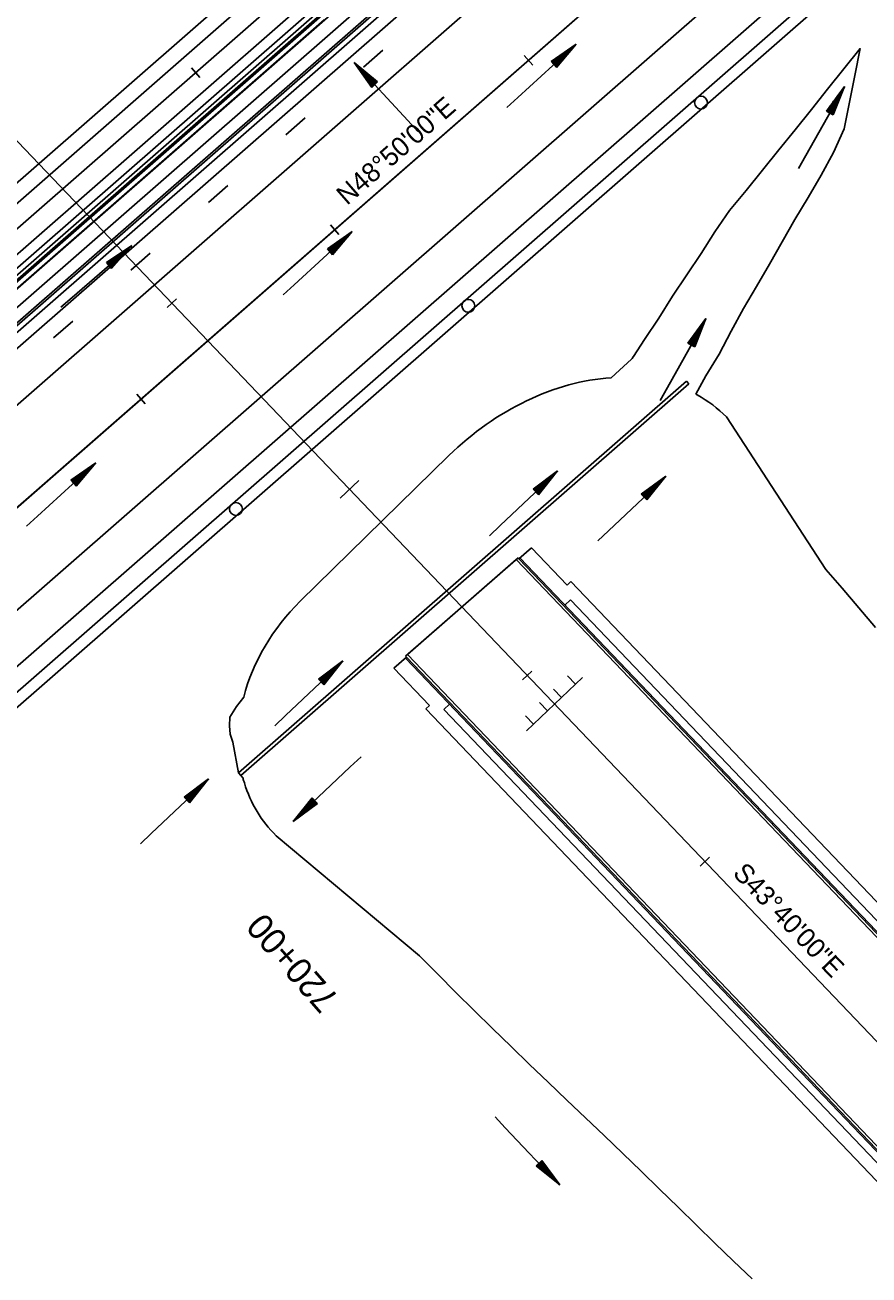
# Model space of a CAD drawing. Extents: x 1300404 to 1323571, y 234004 to 252077.
# Drawn here: x 1310716.2 to 1311044.1, y 240637.1 to 241122.9 of the extents above; entities that cross this region are included whole.
import ezdxf

# ---------------------------------------------------------------- set-up
doc = ezdxf.new("R2010")
doc.units = 0
for name, color, linetype in [('MOT Stage 1', 7, 'Continuous'), ('R_Barrel', 7, 'Continuous'), ('R_Barrier Wall', 7, 'Continuous'), ('R_Bridge', 7, 'Continuous'), ('R_Bridge Wall', 7, 'Continuous'), ('R_Const Limits', 7, 'Continuous'), ('R_Curb', 7, 'Continuous'), ('R_Draft', 7, 'Continuous'), ('R_Flow Arrows', 7, 'Continuous'), ('R_Horz Alg Major Ticks', 7, 'Continuous'), ('R_Horz Alg Minor Ticks', 7, 'Continuous'), ('R_Horz Alg Station Annot', 7, 'Continuous'), ('R_Horz Alg Tangents Text', 7, 'Continuous'), ('R_Lane Edge', 7, 'Continuous'), ('R_Pipe Culvert', 7, 'Continuous'), ('R_Proposed', 7, 'Continuous'), ('R_Shoulder', 7, 'Continuous'), ('R_Sidewalk Edge', 7, 'Continuous'), ('R_Temp Barrier Wall', 7, 'Continuous'), ('R_Temp Travel Stripe', 7, 'Continuous')]:
    doc.layers.add(name, color=color, linetype=linetype)

msp = doc.modelspace()

# ---------------------------------------------------------------- linework, layer by layer
at = {"layer": 'MOT Stage 1'}
for p, q in [((1310921.92, 240858.93), (1310932.77, 240869.29)), ((1310930.05, 240866.7), (1310926.95, 240869.96)), ((1310924.63, 240861.52), (1310921.52, 240864.78)), ((1310911.06, 240848.58), (1310921.92, 240858.93)), ((1310919.2, 240856.34), (1310916.1, 240859.6)), ((1310913.78, 240851.17), (1310910.67, 240854.42))]:
    msp.add_line(p, q, dxfattribs=at)
at = {"layer": 'R_Barrel'}
for centre in [(1310978.82, 241092.72), (1310888.47, 241013.74), (1310798.13, 240934.76)]:
    msp.add_circle(centre, 2.5, dxfattribs=at)
at = {"layer": 'R_Barrier Wall'}
for p, q in [((1309593.62, 240046.84), (1310923.44, 241209.65)), ((1309594.93, 240045.34), (1310924.76, 241208.15))]:
    msp.add_line(p, q, dxfattribs=at)
at = {"layer": 'R_Bridge'}
for p, q in [((1310864.08, 240877.52), (1310907.78, 240915.74)), ((1310907.78, 240915.74), (1310908.12, 240915.39)), ((1310908.12, 240915.39), (1310912.99, 240919.65)), ((1310912.99, 240919.65), (1310926.82, 240905.21)), ((1310926.82, 240905.21), (1310928.27, 240906.59)), ((1310859.51, 240872.89), (1310864.41, 240877.18)), ((1310864.41, 240877.18), (1310864.08, 240877.52)), ((1310873.32, 240858.43), (1310859.51, 240872.89)), ((1310871.88, 240857.04), (1310873.32, 240858.43))]:
    msp.add_line(p, q, dxfattribs=at)
at = {"layer": 'R_Bridge Wall'}
for p, q in [((1310799.12, 240832.17), (1310973.27, 240984.44)), ((1310800, 240831.16), (1310974.14, 240983.43)), ((1310974.14, 240983.43), (1310973.27, 240984.44)), ((1310800, 240831.16), (1310799.12, 240832.17))]:
    msp.add_line(p, q, dxfattribs=at)
at = {"layer": 'R_Const Limits'}
for p, q in [((1310988.78, 240970.54), (1311027.32, 240911.3)), ((1310988.78, 240970.54), (1311027.32, 240911.3)), ((1310823.12, 240898.9), (1310880.92, 240955.54)), ((1310823.12, 240898.9), (1310880.92, 240955.54)), ((1310799.12, 240832.17), (1310800.89, 240830.14)), ((1310799.12, 240832.17), (1310800.89, 240830.14)), ((1310813.77, 240807.78), (1310869.51, 240761.06)), ((1310813.77, 240807.78), (1310869.51, 240761.06))]:
    msp.add_line(p, q, dxfattribs=at)
for points in [[(1310943.96, 240985.79), (1310947.24, 240988.69), (1310951.89, 240992.93), (1310952.15, 240993.31), (1310952.55, 240993.92), (1310952.65, 240994.08), (1310956.95, 241000.61), (1310962.45, 241008.98), (1310967.82, 241017.42), (1310973.35, 241025.76), (1310978.89, 241034.1), (1310984.27, 241042.54), (1310989.93, 241050.81), (1310996.41, 241058.59), (1311002.8, 241066.42), (1311009.11, 241074.29), (1311015.49, 241082.13), (1311021.8, 241090.01), (1311028.05, 241097.93), (1311034.31, 241105.84), (1311040.66, 241113.69), (1311038.66, 241103.24), (1311036.53, 241092.87), (1311034.46, 241082.46), (1311030.27, 241073.32), (1311025.53, 241064.5), (1311020.53, 241055.84), (1311015.36, 241047.28), (1311010.37, 241038.61), (1311005.4, 241029.93), (1311000.43, 241021.25), (1310995.33, 241012.65), (1310990.62, 241003.82), (1310985.89, 240995), (1310980.66, 240986.47), (1310976.81, 240979.35)], [(1310943.96, 240985.79), (1310947.24, 240988.69), (1310951.89, 240992.93), (1310952.15, 240993.31), (1310952.55, 240993.92), (1310952.65, 240994.08), (1310956.95, 241000.61), (1310962.45, 241008.98), (1310967.82, 241017.42), (1310973.35, 241025.76), (1310978.89, 241034.1), (1310984.27, 241042.54), (1310989.93, 241050.81), (1310996.41, 241058.59), (1311002.8, 241066.42), (1311009.11, 241074.29), (1311015.49, 241082.13), (1311021.8, 241090.01), (1311028.05, 241097.93), (1311034.31, 241105.84), (1311040.66, 241113.69), (1311038.66, 241103.24), (1311036.53, 241092.87), (1311034.46, 241082.46), (1311030.27, 241073.32), (1311025.53, 241064.5), (1311020.53, 241055.84), (1311015.36, 241047.28), (1311010.37, 241038.61), (1311005.4, 241029.93), (1311000.43, 241021.25), (1310995.33, 241012.65), (1310990.62, 241003.82), (1310985.89, 240995), (1310980.66, 240986.47), (1310976.81, 240979.35)], [(1311027.33, 240911.29), (1311033.68, 240903.93), (1311040.19, 240896.32), (1311046.68, 240888.7)], [(1311027.33, 240911.29), (1311033.68, 240903.93), (1311040.19, 240896.32), (1311046.68, 240888.7)], [(1310799.12, 240832.17), (1310796.95, 240844.17), (1310795.93, 240847.21), (1310795.63, 240850.43), (1310795.75, 240853.8), (1310798.3, 240857.98), (1310801.17, 240861.66)], [(1310799.12, 240832.17), (1310796.95, 240844.17), (1310795.93, 240847.21), (1310795.63, 240850.43), (1310795.75, 240853.8), (1310798.3, 240857.98), (1310801.17, 240861.66)], [(1310998.7, 240635.54), (1310991.49, 240642.48), (1310984.28, 240649.42), (1310977.09, 240656.38), (1310969.93, 240663.37), (1310962.78, 240670.37), (1310955.65, 240677.39), (1310948.44, 240684.33), (1310941.18, 240691.23), (1310933.93, 240698.14), (1310926.7, 240705.05), (1310919.48, 240711.99), (1310912.27, 240718.93), (1310905.07, 240725.89), (1310897.89, 240732.85), (1310890.72, 240739.83), (1310883.57, 240746.83), (1310876.53, 240753.94), (1310869.51, 240761.06), (1310869.51, 240761.06), (1310869.51, 240761.06), (1310869.51, 240761.06), (1310869.51, 240761.06), (1310869.51, 240761.06), (1310869.51, 240761.06), (1310869.51, 240761.06), (1310869.51, 240761.06)], [(1310998.7, 240635.54), (1310991.49, 240642.48), (1310984.28, 240649.42), (1310977.09, 240656.38), (1310969.93, 240663.37), (1310962.78, 240670.37), (1310955.65, 240677.39), (1310948.44, 240684.33), (1310941.18, 240691.23), (1310933.93, 240698.14), (1310926.7, 240705.05), (1310919.48, 240711.99), (1310912.27, 240718.93), (1310905.07, 240725.89), (1310897.89, 240732.85), (1310890.72, 240739.83), (1310883.57, 240746.83), (1310876.53, 240753.94), (1310869.51, 240761.06), (1310869.51, 240761.06), (1310869.51, 240761.06), (1310869.51, 240761.06), (1310869.51, 240761.06), (1310869.51, 240761.06), (1310869.51, 240761.06), (1310869.51, 240761.06), (1310869.51, 240761.06)]]:
    msp.add_lwpolyline(points, dxfattribs=at)
for centre, major_axis, ratio, start_param, end_param in [((1310926.5, 240908.22), (-62.28, -62.32), 0.745616, 3.84485, 4.698226), ((1310926.5, 240908.22), (-62.28, -62.32), 0.745616, 3.84485, 4.698226), ((1310926.5, 240908.22), (-62.28, -62.32), 0.745616, 3.358393, 3.367118), ((1310926.5, 240908.22), (-62.28, -62.32), 0.745616, 3.358393, 3.367118), ((1310926.5, 240908.22), (-62.28, -62.32), 0.745616, 3.141593, 3.358393), ((1310926.5, 240908.22), (-62.28, -62.32), 0.745616, 3.141593, 3.358393), ((1310862.67, 240857.7), (48.9, 49.92), 0.817242, 1.545592, 2.183789), ((1310862.67, 240857.7), (48.9, 49.92), 0.817242, 1.545592, 2.183789), ((1310862.67, 240857.7), (48.9, 49.92), 0.817242, 2.691395, 2.723332), ((1310862.67, 240857.7), (48.9, 49.92), 0.817242, 2.691395, 2.723332), ((1310862.67, 240857.7), (48.9, 49.92), 0.817242, 2.723644, 3.141593), ((1310862.67, 240857.7), (48.9, 49.92), 0.817242, 2.723644, 3.141593)]:
    msp.add_ellipse(centre, major_axis=major_axis, ratio=ratio, start_param=start_param, end_param=end_param, dxfattribs=at)
at = {"layer": 'R_Curb'}
for p, q in [((1310908.12, 240915.39), (1311065.94, 240750.04)), ((1310908.49, 240915.72), (1311067.92, 240748.69)), ((1310864.04, 240876.85), (1311009.39, 240724.57)), ((1310864.41, 240877.18), (1311008.13, 240726.61)), ((1311008.13, 240726.61), (1311199.03, 240526.61)), ((1311009.39, 240724.57), (1311198.47, 240526.48))]:
    msp.add_line(p, q, dxfattribs=at)
at = {"layer": 'R_Draft'}
for p, q in [((1308396.96, 238971.92), (1312368.36, 242444.53)), ((1308407.83, 238959.5), (1312379.22, 242432.11)), ((1308447.32, 238914.33), (1312418.71, 242386.94)), ((1308458.18, 238901.91), (1312429.57, 242374.52)), ((1309184.47, 239689.08), (1312131.36, 242265.86)), ((1309037.78, 239548.19), (1312137.61, 242258.71)), ((1309193.69, 239678.54), (1312140.58, 242255.32)), ((1309413.86, 239721.62), (1312065.67, 242040.38)), ((1309410.89, 239725), (1311987.97, 241978.41)), ((1309410.89, 239725), (1311987.97, 241978.41))]:
    msp.add_line(p, q, dxfattribs=at)
at = {"layer": 'R_Flow Arrows'}
for p, q in [((1310920.59, 241108.65), (1310930.28, 241115.48)), ((1310922.65, 241106.41), (1310930.28, 241115.48)), ((1310853.18, 241100.72), (1310844.02, 241108.24)), ((1310850.97, 241098.64), (1310844.02, 241108.24)), ((1310920.59, 241108.65), (1310922.65, 241106.41)), ((1310850.97, 241098.64), (1310853.18, 241100.72)), ((1311027.56, 241089.44), (1311034.57, 241098.99)), ((1311030.22, 241087.97), (1311034.57, 241098.99)), ((1311027.56, 241089.44), (1311030.22, 241087.97)), ((1310833.66, 241035.82), (1310843.35, 241042.65)), ((1310835.72, 241033.58), (1310843.35, 241042.65)), ((1310747.81, 241030.54), (1310757.64, 241037.17)), ((1310749.82, 241028.26), (1310757.64, 241037.17)), ((1310833.66, 241035.82), (1310835.72, 241033.58)), ((1310747.81, 241030.54), (1310749.82, 241028.26)), ((1310973.77, 240999.27), (1310980.78, 241008.82)), ((1310976.43, 240997.8), (1310980.78, 241008.82)), ((1310973.77, 240999.27), (1310976.43, 240997.8)), ((1310733.97, 240945.92), (1310743.66, 240952.75)), ((1310736.03, 240943.68), (1310743.66, 240952.75)), ((1310913.58, 240942.49), (1310923.08, 240949.56)), ((1310915.69, 240940.3), (1310923.08, 240949.56)), ((1310733.97, 240945.92), (1310736.03, 240943.68)), ((1310955.66, 240940.48), (1310965.17, 240947.56)), ((1310957.78, 240938.3), (1310965.17, 240947.56)), ((1310913.58, 240942.49), (1310915.69, 240940.3)), ((1310955.66, 240940.48), (1310957.78, 240938.3)), ((1310830.17, 240868.66), (1310839.68, 240875.73)), ((1310832.29, 240866.47), (1310839.68, 240875.73)), ((1310830.17, 240868.66), (1310832.29, 240866.47)), ((1310777.97, 240822.77), (1310787.48, 240829.84)), ((1310780.09, 240820.58), (1310787.48, 240829.84)), ((1310777.97, 240822.77), (1310780.09, 240820.58)), ((1310827.75, 240822.53), (1310820.36, 240813.27)), ((1310829.86, 240820.34), (1310827.75, 240822.53)), ((1310829.86, 240820.34), (1310820.36, 240813.27)), ((1310916.94, 240681.6), (1310914.75, 240679.49)), ((1310914.75, 240679.49), (1310924.01, 240672.1)), ((1310916.94, 240681.6), (1310924.01, 240672.1))]:
    msp.add_line(p, q, dxfattribs=at)
for points in [[(1310903.41, 241090.79), (1310907.64, 241094.7), (1310930.28, 241115.48)], [(1310921.42, 241107.76), (1310926, 241111.96), (1310928.35, 241114.11)], [(1310920.8, 241108.43), (1310922.53, 241110.02)], [(1310921.01, 241108.21), (1310924.47, 241111.38)], [(1310921.21, 241107.98), (1310925.79, 241112.19), (1310926.41, 241112.75)], [(1310921.83, 241107.31), (1310926.41, 241111.51), (1310928.76, 241113.66)], [(1310922.03, 241107.09), (1310926.61, 241111.29), (1310927.23, 241111.85)], [(1310922.24, 241106.86), (1310925.7, 241110.04)], [(1310868.86, 241081.51), (1310864.95, 241085.73), (1310844.13, 241108.34)], [(1310851.85, 241099.47), (1310847.59, 241104), (1310845.42, 241106.32)], [(1310852.3, 241099.89), (1310848.04, 241104.42), (1310845.86, 241106.74)], [(1310851.63, 241099.26), (1310847.37, 241103.79), (1310846.8, 241104.4)], [(1310852.52, 241100.09), (1310848.26, 241104.62), (1310847.69, 241105.23)], [(1310922.44, 241106.64), (1310924.18, 241108.23)], [(1310851.41, 241099.05), (1310848.19, 241102.48)], [(1310852.74, 241100.3), (1310849.52, 241103.73)], [(1310851.19, 241098.84), (1310849.58, 241100.56)], [(1310852.96, 241100.51), (1310851.35, 241102.22)], [(1311016.73, 241067.16), (1311019.56, 241072.18), (1311034.7, 241098.92)], [(1311028.36, 241089), (1311031.36, 241094.45), (1311031.77, 241095.17)], [(1311028.62, 241088.86), (1311031.63, 241094.3), (1311033.18, 241097.08)], [(1311029.16, 241088.56), (1311032.16, 241094), (1311033.71, 241096.78)], [(1311029.42, 241088.41), (1311032.43, 241093.86), (1311032.83, 241094.58)], [(1311027.82, 241089.3), (1311028.96, 241091.35)], [(1311028.09, 241089.15), (1311030.36, 241093.26)], [(1311029.69, 241088.27), (1311031.96, 241092.38)], [(1311029.95, 241088.12), (1311031.09, 241090.18)], [(1310816.47, 241017.96), (1310820.71, 241021.87), (1310843.35, 241042.65)], [(1310834.49, 241034.92), (1310839.07, 241039.13), (1310841.42, 241041.27)], [(1310730.11, 241013.21), (1310734.47, 241016.99), (1310757.73, 241037.06)], [(1310833.87, 241035.6), (1310835.6, 241037.19)], [(1310834.07, 241035.37), (1310837.54, 241038.55)], [(1310834.28, 241035.15), (1310838.86, 241039.35), (1310839.48, 241039.92)], [(1310834.9, 241034.48), (1310839.48, 241038.68), (1310841.83, 241040.82)], [(1310835.1, 241034.25), (1310839.68, 241038.46), (1310840.3, 241039.02)], [(1310835.31, 241034.03), (1310838.77, 241037.21)], [(1310748.02, 241030.32), (1310749.78, 241031.87)], [(1310748.22, 241030.09), (1310751.74, 241033.19)], [(1310748.42, 241029.86), (1310753.08, 241033.97), (1310753.71, 241034.52)], [(1310748.62, 241029.63), (1310753.28, 241033.74), (1310755.68, 241035.84)], [(1310749.02, 241029.18), (1310753.69, 241033.28), (1310756.08, 241035.38)], [(1310749.22, 241028.95), (1310753.89, 241033.06), (1310754.51, 241033.6)], [(1310749.42, 241028.72), (1310752.95, 241031.83)], [(1310835.51, 241033.8), (1310837.24, 241035.39)], [(1310749.62, 241028.49), (1310751.39, 241030.04)], [(1310962.94, 240976.98), (1310965.77, 240982.01), (1310980.91, 241008.74)], [(1310974.3, 240998.97), (1310976.57, 241003.09)], [(1310974.57, 240998.83), (1310977.57, 241004.27), (1310977.98, 241005)], [(1310974.83, 240998.68), (1310977.84, 241004.12), (1310979.39, 241006.9)], [(1310975.36, 240998.39), (1310978.37, 241003.83), (1310979.92, 241006.61)], [(1310975.63, 240998.24), (1310978.64, 241003.68), (1310979.04, 241004.41)], [(1310974.03, 240999.12), (1310975.17, 241001.18)], [(1310975.9, 240998.09), (1310978.17, 241002.21)], [(1310976.16, 240997.94), (1310977.3, 241000)], [(1310716.78, 240928.06), (1310721.02, 240931.97), (1310743.65, 240952.75)], [(1310734.59, 240945.25), (1310739.17, 240949.46), (1310739.78, 240950.02)], [(1310734.79, 240945.03), (1310739.37, 240949.23), (1310741.73, 240951.38)], [(1310735.2, 240944.58), (1310739.79, 240948.78), (1310742.14, 240950.93)], [(1310735.41, 240944.35), (1310739.99, 240948.56), (1310740.6, 240949.12)], [(1310896.7, 240924.36), (1310900.87, 240928.34), (1310923.19, 240949.45)], [(1310734.18, 240945.7), (1310735.91, 240947.29)], [(1310734.38, 240945.48), (1310737.85, 240948.65)], [(1310735.62, 240944.13), (1310739.08, 240947.31)], [(1310735.82, 240943.91), (1310737.55, 240945.5)], [(1310914, 240942.05), (1310917.38, 240945.32)], [(1310914.21, 240941.83), (1310918.68, 240946.15), (1310919.29, 240946.73)], [(1310914.42, 240941.61), (1310918.9, 240945.94), (1310921.19, 240948.14)], [(1310914.85, 240941.18), (1310919.32, 240945.5), (1310921.61, 240947.7)], [(1310915.06, 240940.96), (1310919.53, 240945.28), (1310920.13, 240945.86)], [(1310915.27, 240940.74), (1310918.65, 240944.01)], [(1310938.78, 240922.35), (1310942.95, 240926.33), (1310965.27, 240947.45)], [(1310956.3, 240939.83), (1310960.77, 240944.15), (1310961.37, 240944.73)], [(1310956.51, 240939.61), (1310960.98, 240943.93), (1310963.27, 240946.13)], [(1310956.93, 240939.17), (1310961.4, 240943.49), (1310963.69, 240945.7)], [(1310913.79, 240942.27), (1310915.48, 240943.9)], [(1310915.48, 240940.52), (1310917.17, 240942.15)], [(1310955.87, 240940.27), (1310957.56, 240941.9)], [(1310956.08, 240940.05), (1310959.46, 240943.31)], [(1310957.14, 240938.95), (1310961.61, 240943.27), (1310962.21, 240943.85)], [(1310957.35, 240938.73), (1310960.73, 240942)], [(1310957.56, 240938.52), (1310959.25, 240940.15)], [(1310813.29, 240850.53), (1310817.46, 240854.51), (1310839.78, 240875.62)], [(1310830.6, 240868.22), (1310833.98, 240871.49)], [(1310830.81, 240868), (1310835.28, 240872.33), (1310835.88, 240872.9)], [(1310831.02, 240867.79), (1310835.49, 240872.11), (1310837.79, 240874.31)], [(1310831.44, 240867.35), (1310835.91, 240871.67), (1310838.21, 240873.87)], [(1310831.65, 240867.13), (1310836.12, 240871.45), (1310836.72, 240872.03)], [(1310830.39, 240868.44), (1310832.08, 240870.08)], [(1310831.87, 240866.91), (1310835.24, 240870.18)], [(1310832.08, 240866.69), (1310833.77, 240868.33)], [(1310846.75, 240838.47), (1310842.57, 240834.5), (1310820.25, 240813.38)], [(1310761.09, 240804.63), (1310765.26, 240808.61), (1310787.58, 240829.73)], [(1310778.82, 240821.89), (1310783.29, 240826.21), (1310785.58, 240828.42)], [(1310779.24, 240821.45), (1310783.71, 240825.77), (1310786, 240827.98)], [(1310778.18, 240822.55), (1310779.87, 240824.18)], [(1310778.39, 240822.33), (1310781.77, 240825.59)], [(1310778.61, 240822.11), (1310783.08, 240826.43), (1310783.68, 240827.01)], [(1310779.45, 240821.24), (1310783.92, 240825.56), (1310784.52, 240826.13)], [(1310779.66, 240821.02), (1310783.04, 240824.28)], [(1310779.87, 240820.8), (1310781.56, 240822.43)], [(1310828.59, 240821.66), (1310824.12, 240817.34), (1310821.83, 240815.13)], [(1310829.02, 240821.22), (1310824.55, 240816.9), (1310822.25, 240814.69)], [(1310828.38, 240821.87), (1310823.91, 240817.55), (1310823.31, 240816.98)], [(1310829.23, 240821), (1310824.76, 240816.68), (1310824.16, 240816.1)], [(1310828.17, 240822.09), (1310824.79, 240818.83)], [(1310829.44, 240820.78), (1310826.06, 240817.52)], [(1310827.96, 240822.31), (1310826.27, 240820.68)], [(1310829.65, 240820.56), (1310827.96, 240818.93)], [(1310898.81, 240698.49), (1310902.78, 240694.31), (1310923.9, 240671.99)], [(1310914.97, 240679.7), (1310916.6, 240678.01)], [(1310915.19, 240679.91), (1310918.45, 240676.53)], [(1310915.41, 240680.12), (1310919.73, 240675.65), (1310920.3, 240675.05)], [(1310915.63, 240680.33), (1310919.95, 240675.86), (1310922.15, 240673.57)], [(1310916.06, 240680.76), (1310920.38, 240676.29), (1310922.59, 240673.99)], [(1310916.28, 240680.97), (1310920.6, 240676.5), (1310921.18, 240675.9)], [(1310916.5, 240681.18), (1310919.77, 240677.8)], [(1310916.72, 240681.39), (1310918.35, 240679.7)]]:
    msp.add_lwpolyline(points, dxfattribs=at)
at = {"layer": 'R_Horz Alg Major Ticks'}
msp.add_lwpolyline([(1310845.86, 240945.85), (1310838.63, 240938.95)], dxfattribs=at)
msp.add_lwpolyline([(1310845.86, 240945.85), (1310838.63, 240938.95)], dxfattribs=at)
at = {"layer": 'R_Horz Alg Minor Ticks'}
for points in [[(1310910.16, 241111.02), (1310913.45, 241107.26)], [(1310910.16, 241111.02), (1310913.45, 241107.26)], [(1310780.89, 241106.25), (1310784.18, 241102.49)], [(1310780.89, 241106.25), (1310784.18, 241102.49)], [(1310834.88, 241045.2), (1310838.17, 241041.44)], [(1310834.88, 241045.2), (1310838.17, 241041.44)], [(1310775.01, 241016.46), (1310771.39, 241013.01)], [(1310775.01, 241016.46), (1310771.39, 241013.01)], [(1310759.6, 240979.37), (1310762.89, 240975.61)], [(1310759.6, 240979.37), (1310762.89, 240975.61)], [(1310913.1, 240871.79), (1310909.48, 240868.34)], [(1310913.1, 240871.79), (1310909.48, 240868.34)], [(1310982.15, 240799.45), (1310978.53, 240796)], [(1310982.15, 240799.45), (1310978.53, 240796)]]:
    msp.add_lwpolyline(points, dxfattribs=at)
at = {"layer": 'R_Lane Edge'}
for p, q in [((1309254.07, 239731.34), (1311026.82, 241281.45)), ((1309254.07, 239731.34), (1311026.82, 241281.45)), ((1310188.6, 240594.99), (1310884.73, 241203.69)), ((1309589.67, 240051.36), (1310894.61, 241192.4)), ((1310864.83, 240878.18), (1310907.03, 240915.08)), ((1310907.03, 240915.08), (1311239.63, 240566.63)), ((1310864.83, 240878.18), (1311200.16, 240526.88))]:
    msp.add_line(p, q, dxfattribs=at)
at = {"layer": 'R_Pipe Culvert'}
for p, q in [((1310643.68, 240963.19), (1310830.73, 241126.74)), ((1310645.33, 240961.31), (1310832.37, 241124.86))]:
    msp.add_line(p, q, dxfattribs=at)
at = {"layer": 'R_Proposed'}
for p, q in [((1308427.57, 238936.91), (1312793.8, 242754.77)), ((1308427.57, 238936.91), (1312793.8, 242754.77)), ((1309180.37, 239595.16), (1312398.96, 242409.52)), ((1309180.37, 239595.16), (1312398.96, 242409.52)), ((1310151.78, 241665.77), (1311952.58, 239779.15)), ((1310151.78, 241665.77), (1311952.58, 239779.15)), ((1310165.59, 241651.3), (1311952.63, 239779.09)), ((1310165.59, 241651.3), (1311952.63, 239779.09)), ((1310165.59, 241651.3), (1311952.63, 239779.09)), ((1310165.59, 241651.3), (1311952.63, 239779.09)), ((1309584.71, 240056.98), (1310889.67, 241198.05)), ((1309584.71, 240056.98), (1310889.67, 241198.05))]:
    msp.add_line(p, q, dxfattribs=at)
at = {"layer": 'R_Shoulder'}
for p, q in [((1309482.39, 239944.26), (1311020.24, 241288.97)), ((1309482.39, 239944.26), (1311020.24, 241288.97)), ((1310239.17, 240647.18), (1310880.78, 241208.21)), ((1309592.3, 240048.35), (1310897.24, 241189.39))]:
    msp.add_line(p, q, dxfattribs=at)
at = {"layer": 'R_Sidewalk Edge'}
for p, q in [((1310928.27, 240906.59), (1311249.89, 240569.63)), ((1310925.93, 240897.45), (1310928.1, 240899.52)), ((1310928.1, 240899.52), (1311244.64, 240567.9)), ((1310871.88, 240857.04), (1311196.44, 240517.02)), ((1310881.12, 240858.95), (1310878.95, 240856.88)), ((1310878.95, 240856.88), (1311198.54, 240522.06))]:
    msp.add_line(p, q, dxfattribs=at)
at = {"layer": 'R_Temp Barrier Wall'}
for points in [[(1311027.31, 241280.88), (1310559.74, 240872.07), (1309471.94, 239921.22), (1308468.86, 239041.61)], [(1311028.63, 241279.38), (1310561.08, 240870.59), (1309473.28, 239919.73), (1308470.17, 239040.11)]]:
    msp.add_lwpolyline(points, dxfattribs=at)
at = {"layer": 'R_Temp Travel Stripe'}
for p, q in [((1310855.19, 241113.12), (1310847.66, 241106.54)), ((1310825.08, 241086.8), (1310817.55, 241080.21)), ((1310794.96, 241060.47), (1310787.43, 241053.89)), ((1310764.85, 241034.14), (1310757.32, 241027.56)), ((1310734.74, 241007.81), (1310727.21, 241001.23))]:
    msp.add_line(p, q, dxfattribs=at)

# ---------------------------------------------------------------- texts
at = {"layer": 'R_Horz Alg Station Annot'}
msp.add_text('720+00', height=10, rotation=131.1667, dxfattribs=at).set_placement((1310838.66, 240744.64))
msp.add_text('720+00', height=10, rotation=131.1667, dxfattribs=at).set_placement((1310838.66, 240744.64))
at = {"layer": 'R_Horz Alg Tangents Text'}
for s, rotation, p in [('N48%%d50\'00"E', 41.1667, (1310841.31, 241052.54)), ('N48%%d50\'00"E', 41.1667, (1310841.31, 241052.54)), ('S43%%d40\'00"E', 313.6667, (1310990.83, 240792.85)), ('S43%%d40\'00"E', 313.6667, (1310990.83, 240792.85))]:
    msp.add_text(s, height=7.5, rotation=rotation, dxfattribs=at).set_placement(p)

doc.saveas('drawing.dxf')
